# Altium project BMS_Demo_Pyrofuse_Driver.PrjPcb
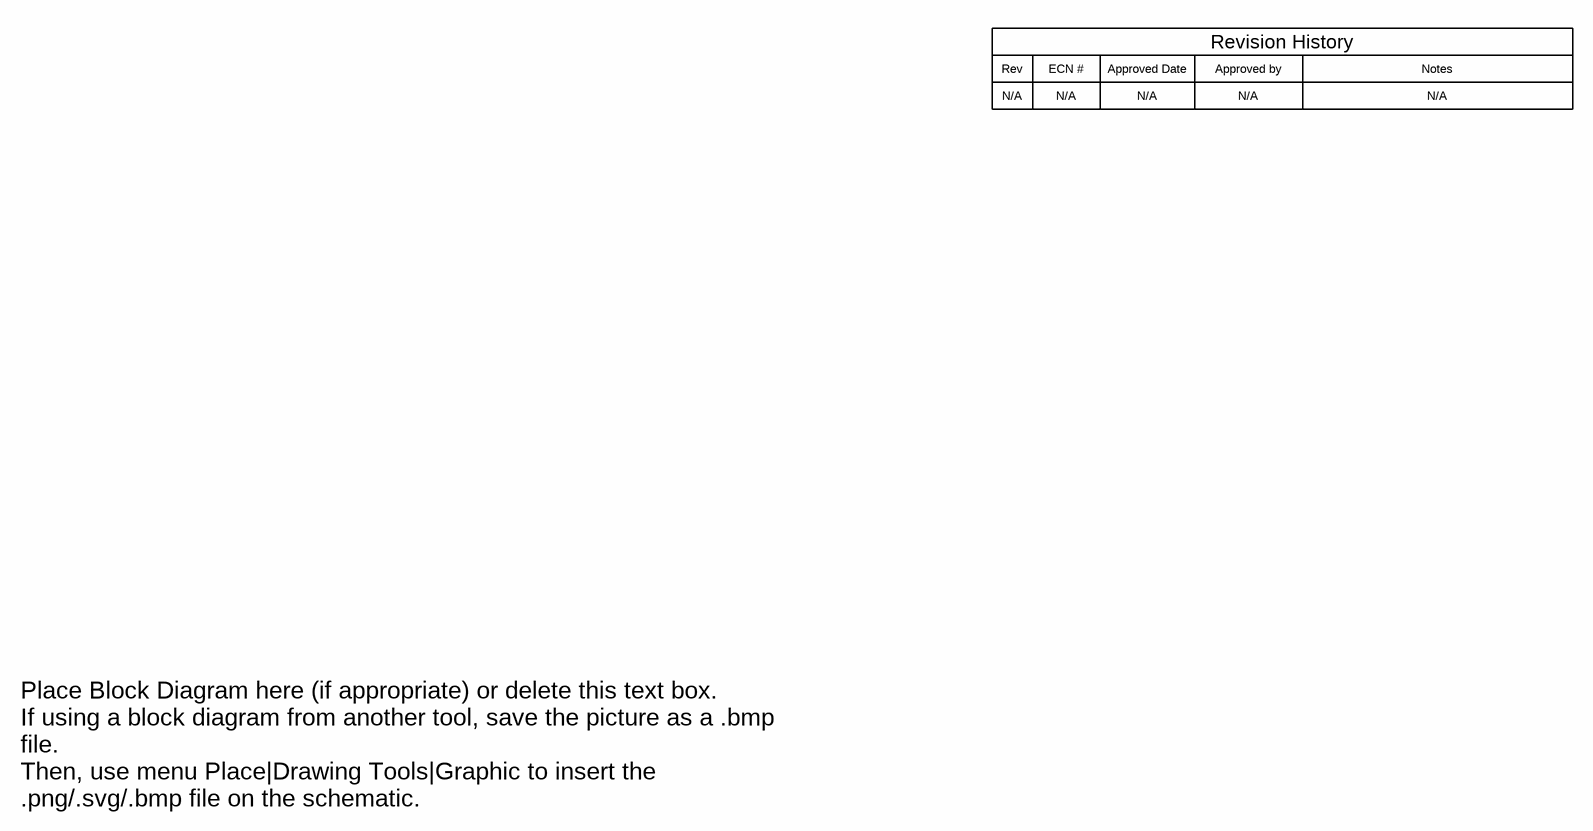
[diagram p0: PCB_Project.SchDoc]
CopyrightYear: 2022; PCB_Layout: A0497701; PCB_Rev: E1; PRJ_Customer: Public Release; PRJ_Engineer: Bing Zou; PRJ_Number: AUTOSYS-783; PRJ_Title: PYROFUSE DRIVER; SCH_Rev: E1; TechSupport: http://www.ti.com/support; TID: N/A
3 sheets, 67 parts. Net scope: global (net labels, ports and power ports of the same name join across sheets).
Board file: BMS_Demo_Pyrofuse_Driver_PCB.PcbDoc
Sheets:
  PCB_Project.SchDoc
  BMS_Demo_Pyrofuse_Driver_Schematic.SchDoc
  BMS_Demo_Pyrufose_Driver_Hardware.SchDoc

## Sheet PCB_Project.SchDoc
size 431 x 279 mm; Date: Not shown in title block; ApprovedBy: Not shown in title block; CheckedBy: Not shown in title block; Author: Not shown in title block; CompanyName: Not shown in title block; Engineer: Not shown in title block; Organization: Not shown in title block; Address1: Not shown in title block; Address2: Not shown in title block; Address3: Not shown in title block; Address4: Not shown in title block; DocumentNumber: 1; Revision: Use project parameter SCH_Rev; SheetNumber: 1; SheetTotal: 3; PageSetup: Record=PageOptions¦CenterHorizontal=True¦CenterVertical=True¦PrintScale=1.00¦XCorrection=1.00¦YCorrection=1.00¦PrintKind=0¦BorderSize=5000000¦LeftOffset=0¦BottomOffset=0¦Orientation=2¦PaperLength=1000¦PaperWidth=1000¦Scale=100¦PaperSource=15¦PrintQuality=600¦MediaType=1¦DitherType=10¦PaperKind=Letter¦PrintScaleMode=1

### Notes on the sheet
- Rev
- N/A
- ECN #
- Approved Date
- Approved by
- Revision History
- Notes
- Place Block Diagram here (if appropriate) or delete this text box.
  If using a block diagram from another tool, save the picture as a .bmp file.
  Then, use menu Place|Drawing Tools|Graphic to insert the .png/.svg/.bmp file on the schematic.

## Sheet BMS_Demo_Pyrofuse_Driver_Schematic.SchDoc
size 431 x 279 mm; Date: Not shown in title block; ApprovedBy: Not shown in title block; CheckedBy: Not shown in title block; Author: Not shown in title block; CompanyName: Not shown in title block; Engineer: Not shown in title block; Organization: Not shown in title block; Address1: Not shown in title block; Address2: Not shown in title block; Address3: Not shown in title block; Address4: Not shown in title block; DocumentNumber: 2; Revision: Use project parameter SCH_Rev; SheetNumber: 2; SheetTotal: 3; PageSetup: Record=PageOptions¦CenterHorizontal=True¦CenterVertical=True¦PrintScale=1.00¦XCorrection=1.00¦YCorrection=1.00¦PrintKind=0¦BorderSize=5000000¦LeftOffset=0¦BottomOffset=0¦Orientation=2¦PaperLength=1000¦PaperWidth=1000¦Scale=100¦PaperSource=15¦PrintQuality=600¦MediaType=1¦DitherType=10¦PaperKind=Letter¦PrintScaleMode=1
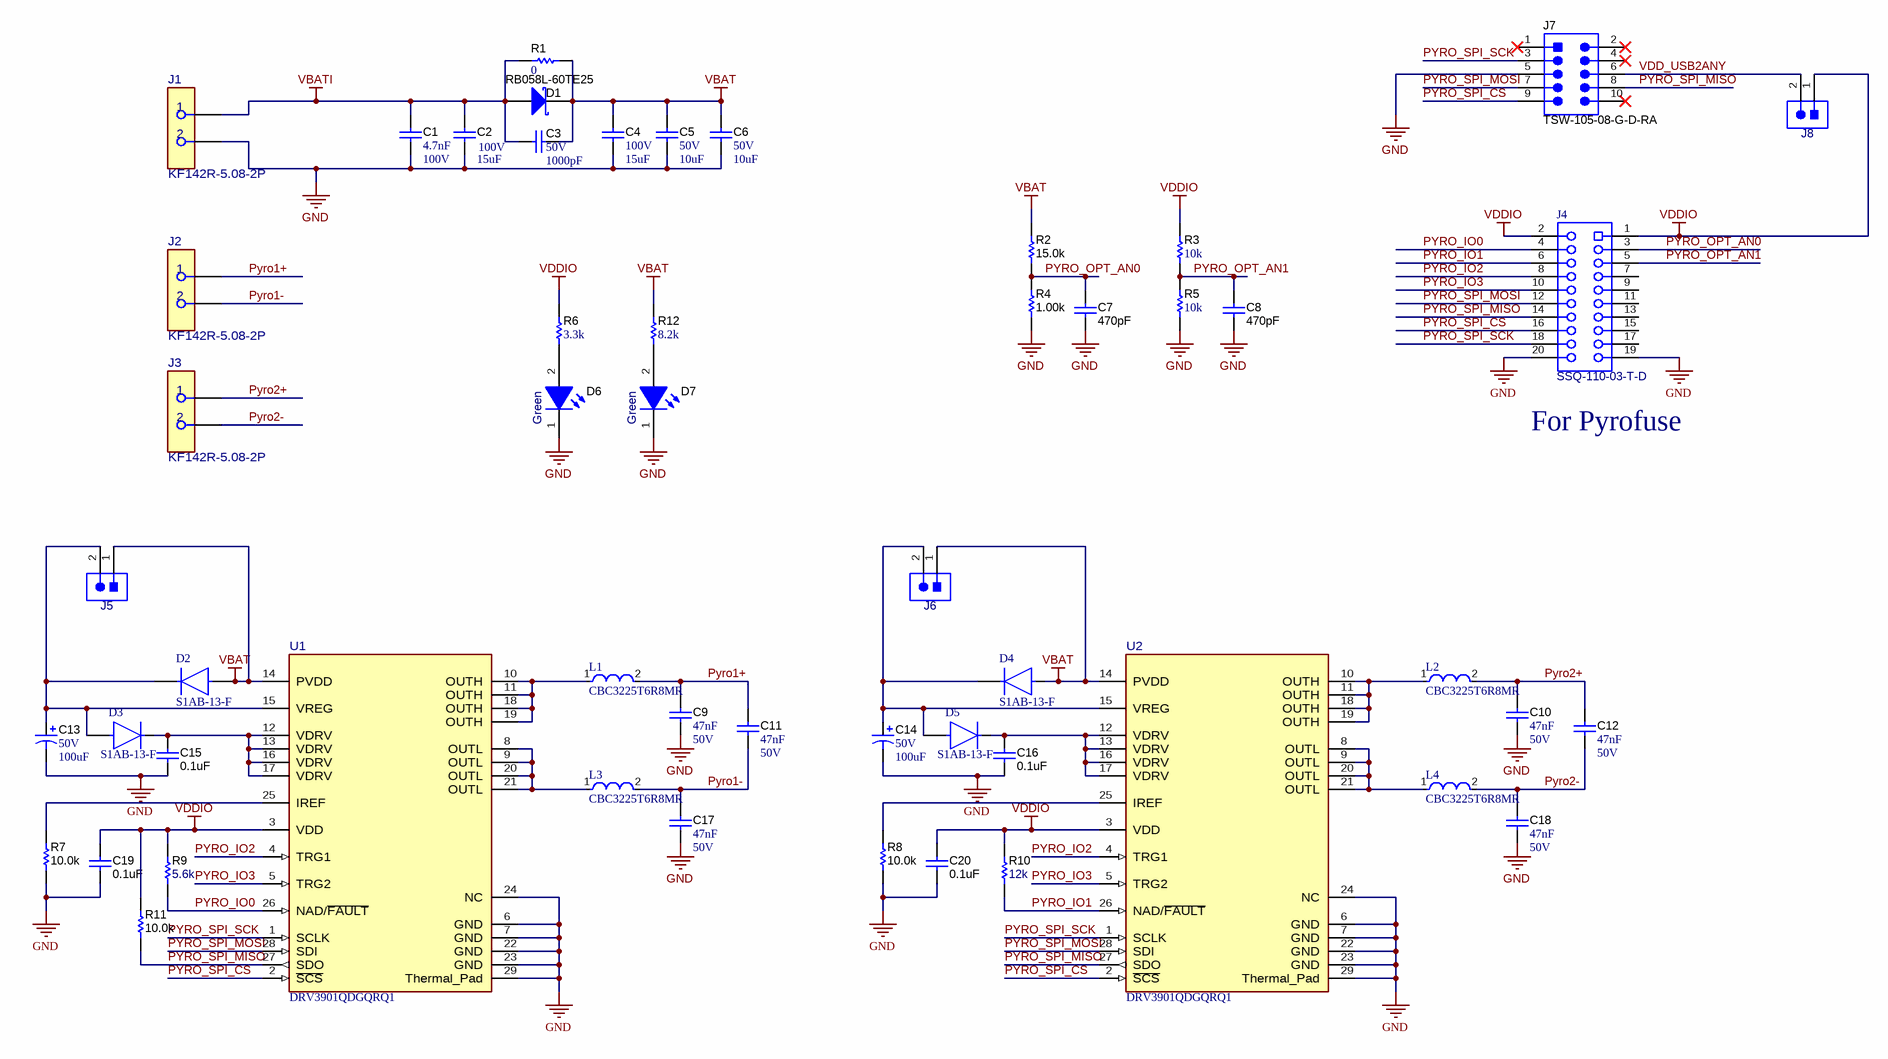
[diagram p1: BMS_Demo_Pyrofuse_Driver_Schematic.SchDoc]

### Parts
C1  Cap_F: 4.7nF  VDC_V: 100V  [0603]  (hidden comment: CGA3E2X7R2A472K080AA)
C2  VDC_V: 100V  ValueDisplayed: 15uF  [2220_280]  (hidden comment: CGA9P3X7S2A156M250KB)
C3  VDC_V: 50V  ValueDisplayed: 1000pF  [0402]  (hidden comment: GRM1555C1H102JA01D)
C4  VDC_V: 100V  ValueDisplayed: 15uF  [2220_280]  (hidden comment: CGA9P3X7S2A156M250KB)
C5  VDC_V: 50V  ValueDisplayed: 10uF  [1210_280]  (hidden comment: CGA6P3X7S1H106K250AB)
C6  VDC_V: 50V  ValueDisplayed: 10uF  [1210_280]  (hidden comment: CGA6P3X7S1H106K250AB)
C7  ValueDisplayed: 470pF  [0402L]  (hidden comment: GRM155R71H471KA01D)
C8  ValueDisplayed: 470pF  [0402L]  (hidden comment: GRM155R71H471KA01D)
C9  Cap_F: 47nF  VDC_V: 50V  [0603]  (hidden comment: CGA3E2X7R1H473K080AA)
C10  Cap_F: 47nF  VDC_V: 50V  [0603]  (hidden comment: CGA3E2X7R1H473K080AA)
C11  Cap_F: 47nF  VDC_V: 50V  [0603]  (hidden comment: CGA3E2X7R1H473K080AA)
C12  Cap_F: 47nF  VDC_V: 50V  [0603]  (hidden comment: CGA3E2X7R1H473K080AA)
C13  VDC_V: 50V  ValueDisplayed: 100uF  [Chemi-Con_800x1200]  (hidden comment: ELXZ500ELL101MH12D)
C14  VDC_V: 50V  ValueDisplayed: 100uF  [Chemi-Con_800x1200]  (hidden comment: ELXZ500ELL101MH12D)
C15  ValueDisplayed: 0.1uF  [0402L]  (hidden comment: C1005X7R1H104K050BE)
C16  ValueDisplayed: 0.1uF  [0402L]  (hidden comment: C1005X7R1H104K050BE)
C17  Cap_F: 47nF  VDC_V: 50V  [0603]  (hidden comment: CGA3E2X7R1H473K080AA)
C18  Cap_F: 47nF  VDC_V: 50V  [0603]  (hidden comment: CGA3E2X7R1H473K080AA)
C19  ValueDisplayed: 0.1uF  [0402L]  (hidden comment: C1005X7R1H104K050BE)
C20  ValueDisplayed: 0.1uF  [0402L]  (hidden comment: C1005X7R1H104K050BE)
D1  RB058L-60TE25  [SMA]
D2  S1AB-13-F  [FP-SMB-MFG]
D3  S1AB-13-F  [FP-SMB-MFG]
D4  S1AB-13-F  [FP-SMB-MFG]
D5  S1AB-13-F  [FP-SMB-MFG]
D6  value Green  [WL-SMCW_GREEN]  (hidden comment: 150060VS75000)
D7  value Green  [WL-SMCW_GREEN]  (hidden comment: 150060VS75000)
J1  KF142R-5.08-2P  [FP-KF142R-5.08-2P_HDR2-MFG]
J2  KF142R-5.08-2P  [FP-KF142R-5.08-2P_HDR2-MFG]
J3  KF142R-5.08-2P  [FP-KF142R-5.08-2P_HDR2-MFG]
J4  SSQ-110-03-T-D  [Samtec_SSQ-110-03-x-D]
J5  PEC02SAAN  [CONN_PEC02SAAN]  (value not drawn)
J6  PEC02SAAN  [CONN_PEC02SAAN]  (value not drawn)
J7  TSW-105-08-G-D-RA  [Samtec_TSW-105-08-G-D-RA]
J8  PEC02SAAN  [CONN_PEC02SAAN]  (value not drawn)
L1  CBC3225T6R8MR  [FP-CB3225-MFG]
L2  CBC3225T6R8MR  [FP-CB3225-MFG]
L3  CBC3225T6R8MR  [FP-CB3225-MFG]
L4  CBC3225T6R8MR  [FP-CB3225-MFG]
R1  ValueDisplayed: 0  [2512]  (hidden comment: CRCW25120000Z0EG)
R2  ValueDisplayed: 15.0k  [0402L]  (hidden comment: RC0402FR-0715KL)
R3  ValueDisplayed: 10k  [0402]  (hidden comment: CRCW040210K0JNED)
R4  ValueDisplayed: 1.00k  [0402L]  (hidden comment: RC0402FR-071KL)
R5  ValueDisplayed: 10k  [0402]  (hidden comment: CRCW040210K0JNED)
R6  ValueDisplayed: 3.3k  [0603]  (hidden comment: CRCW06033K30JNEA)
R7  ValueDisplayed: 10.0k  [0402]  (hidden comment: CRCW040210K0FKED)
R8  ValueDisplayed: 10.0k  [0402]  (hidden comment: CRCW040210K0FKED)
R9  ValueDisplayed: 5.6k  [0402L]  (hidden comment: CRCW04025K60JNED)
R10  ValueDisplayed: 12k  [0402L]  (hidden comment: CRCW040212K0JNED)
R11  ValueDisplayed: 10.0k  [0402]  (hidden comment: CRCW040210K0FKED)
R12  ValueDisplayed: 8.2k  [0603]  (hidden comment: CRCW06038K20JNEA)
U1  DRV3901QDGQRQ1  [DGQ0028A-MFG]
U2  DRV3901QDGQRQ1  [DGQ0028A-MFG]

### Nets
GND: C1.2 C2.2 C4.2 C5.2 C6.2 C7.2 C8.2 C9.2 C10.2 C13.2(-) C14.2(-) C15.2 C16.2 C17.2 C18.2 C19.1 C20.1 D6.1(K) D7.1(K) J1.2 J4.19 J4.20 J7.5 R4.1 R5.1 R7.1 R8.1 U1.6(GND) U1.7(GND) U1.22(GND) U1.23(GND) U1.24(NC) U1.29(Thermal_Pad) U2.6(GND) U2.7(GND) U2.22(GND) U2.23(GND) U2.24(NC) U2.29(Thermal_Pad)
VBAT: C3.1 C4.1 C5.1 C6.1 D1.1(K) D2.2(A) D4.2(A) J5.1 J6.1 R1.2 R2.2 R12.2 U1.14(PVDD) U2.14(PVDD)
VBATI: C1.1 C2.1 C3.2 D1.2(A) J1.1 R1.1
VDDIO: C19.2 C20.2 J4.1 J4.2 J8.1 R3.2 R6.2 R9.2 R10.2 R11.2 U1.3(VDD) U2.3(VDD)
Pyro1+: C9.1 C11.1 J2.1 L1.2
Pyro1-: C11.2 C17.1 J2.2 L3.2
Pyro2+: C10.1 C12.1 J3.1 L2.2
Pyro2-: C12.2 C18.1 J3.2 L4.2
PYRO_IO0: J4.4 R9.1 U1.26(NAD/~{FAULT})
PYRO_IO1: J4.6 R10.1 U2.26(NAD/~{FAULT})
PYRO_IO2: J4.8 U1.4(TRG1) U2.4(TRG1)
PYRO_IO3: J4.10 U1.5(TRG2) U2.5(TRG2)
PYRO_OPT_AN0: C7.1 J4.3 R2.1 R4.2
PYRO_OPT_AN1: C8.1 J4.5 R3.1 R5.2
PYRO_SPI_CS: J4.16 J7.9 U1.2(~{SCS}) U2.2(~{SCS})
PYRO_SPI_MISO: J4.14 J7.8 R11.1 U1.27(SDO) U2.27(SDO)
PYRO_SPI_MOSI: J4.12 J7.7 U1.28(SDI) U2.28(SDI)
PYRO_SPI_SCK: J4.18 J7.3 U1.1(SCLK) U2.1(SCLK)
VDD_USB2ANY: J7.6 J8.2
NetC13_1: C13.1(+) D2.1(C) D3.2(A) J5.2 U1.15(VREG)
NetC14_1: C14.1(+) D4.1(C) D5.2(A) J6.2 U2.15(VREG)
NetC15_1: C15.1 D3.1(C) U1.12(VDRV) U1.13(VDRV) U1.16(VDRV) U1.17(VDRV)
NetC16_1: C16.1 D5.1(C) U2.12(VDRV) U2.13(VDRV) U2.16(VDRV) U2.17(VDRV)
NetD6_2: D6.2(A) R6.1
NetD7_2: D7.2(A) R12.1
NetL1_1: L1.1 U1.10(OUTH) U1.11(OUTH) U1.18(OUTH) U1.19(OUTH)
NetL2_1: L2.1 U2.10(OUTH) U2.11(OUTH) U2.18(OUTH) U2.19(OUTH)
NetL3_1: L3.1 U1.8(OUTL) U1.9(OUTL) U1.20(OUTL) U1.21(OUTL)
NetL4_1: L4.1 U2.8(OUTL) U2.9(OUTL) U2.20(OUTL) U2.21(OUTL)
NetR7_2: R7.2 U1.25(IREF)
NetR8_2: R8.2 U2.25(IREF)

Not connected (* = marked no-connect by the designer): J4 7 9 11 13 15 17; J7 1* 2* 4* 10*

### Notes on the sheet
- (near J4) For Pyrofuse

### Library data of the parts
C1 = CMP-0007088-4: CAP, CERM, 4700 pF, 100 V, +/- 10%, X7R, AEC-Q200 Grade 1, 0603; Manufacturer: TDK; TaMin_C: -55°C; ESR_ohm: 0.469862; Polarized: N; SizeAreaWB_mm2: 4.68; Value1: 0.469862 ohm; U/M: EA; Value: 4700pF; TaMax_C: 125°C; SizeZ_mm: 1; SizeX_mm: 1.6; SizeY_mm: 0.8; SizeArea_mm2: 1.28; AEC Qualified: Y; IRMS_A: 323.35mA; AEC Category: Q200
C2 C4 = CMP-0009420-2: CAP, CERM, 15 uF, 100 V, +/- 20%, X7S, AEC-Q200 Grade 1, 2220; Manufacturer: TDK; TaMin_C: -55°C; ESR_ohm: 2.642m; Polarized: N; SizeAreaWB_mm2: 53.9; Value1: 0.002642 ohm; U/M: EA; Value: 15uF; TaMax_C: 125°C; SizeZ_mm: 2.8; SizeX_mm: 5.7; SizeY_mm: 5; SizeArea_mm2: 28.5; AEC Qualified: Y; Cap_F: 15µF; IRMS_A: 5.61617A; AEC Grade: 1; AEC Category: Q200
C3 = CMP-0006412-2: CAP, CERM, 1000 pF, 50 V, +/- 5%, C0G/NP0, 0402; Manufacturer: MuRata; TaMin_C: -55°C; Polarized: N; SizeAreaWB_mm2: 3; Value1: Unknown; U/M: EA; Value: 1000pF; TaMax_C: 125°C; SizeZ_mm: 0.6; SizeX_mm: 1; SizeY_mm: 0.5; Cap_F: 1nF; AEC Category: Q200
C5 C6 = CMP-0009164-2: CAP, CERM, 10 uF, 50 V, +/- 10%, X7S, AEC-Q200 Grade 1, 1210; Manufacturer: TDK; TaMin_C: -55°C; ESR_ohm: 2.827m; Polarized: N; SizeAreaWB_mm2: 14.7; Value1: 0.002827 ohm; U/M: EA; Value: 10uF; TaMax_C: 125°C; SizeZ_mm: 2.8; SizeX_mm: 3.2; SizeY_mm: 2.5; SizeArea_mm2: 8; AEC Qualified: Y; Cap_F: 10µF; IRMS_A: 4.37286A; AEC Grade: 1; AEC Category: Q200
C7 C8 = CMP-0006691-2: CAP, CERM, 470 pF, 50 V, +/- 10%, X7R, 0402; Manufacturer: MuRata; TaMin_C: -55°C; Polarized: N; SizeAreaWB_mm2: 3; Value1: Unknown; U/M: EA; Value: 470pF; TaMax_C: 125°C; SizeZ_mm: 0.6; SizeX_mm: 1; SizeY_mm: 0.5; Cap_Case: 0402; Value2: 50V; AEC Category: Q200
C9-C12 C17 C18 = CMP-0007079-4: CAP, CERM, 0.047 uF, 50 V, +/- 10%, X7R, AEC-Q200 Grade 1, 0603; Manufacturer: TDK; TaMin_C: -55°C; ESR_ohm: 0.049007; Polarized: N; SizeAreaWB_mm2: 4.68; Value1: 0.049007 ohm; U/M: EA; TaMax_C: 125°C; SizeZ_mm: 1; SizeX_mm: 1.6; SizeY_mm: 0.8; SizeArea_mm2: 1.28; AEC Qualified: Y; IRMS_A: 7.67528dA; AEC Category: Q200
C13 C14 = CMP-0009893-2: CAP, AL, 100 uF, 50 V, +/- 20%, AEC-Q200 Grade 2, TH; Manufacturer: Chemi-Con; TaMin_C: -55°C; Polarized: Y; SizeAreaWB_mm2: 100; Value1: Unknown; U/M: EA; Value: 100uF; TaMax_C: 105°C; SizeZ_mm: 13.5; SizeX_mm: 8; Cap_Case: 8x12mm; SizeArea_mm2: 64; CompType: Capacitor; Cap_F: 100µF; IRMS_A: 4.85dA; AEC Grade: 2; AEC Category: Q200
C15 C16 C19 C20 = CMP-0064946-2: CAP, CERM, 0.1 uF, 50 V,+/- 10%, X7R, 0402; Manufacturer: TDK; TaMin_C: -55°C; Polarized: N; SizeAreaWB_mm2: 3; Value1: Unknown; U/M: EA; Value: 0.1uF; TaMax_C: 125°C; SizeZ_mm: 0.6; SizeX_mm: 1; SizeY_mm: 0.5; Cap_Case: 0402; Value2: 50V; Cap_F: 100nF; AEC Category: Q200
D1 = CMP-0028854-2: Diode, Schottky, 60 V, 3 A, AEC-Q101, SMA; Manufacturer: Rohm; Value1: 3A; AEC Category: Q101; Green_REACh: Incomplete; TJmax_C: 150°C; SizeArea_mm2: 16.3228; Vf_V: 640mV; SizeZ_mm: 2.87; Value2: 0.64V; Value: 60V; SizeX_mm: 5.59; AEC Qualified: Y; Green_Lifecycle: Not Set; SizeAreaWB_mm2: 37.3428; SizeY_mm: 2.92
D2-D5 = CMP-0586-00001-3: DIODE GEN PURP 50V 1A SMB; Element Configuration: Single; Max Surge Current: 30A; Polarity: Standard; Recovery Time: 1.8us; Forward Voltage: 1.1V; Capacitance: 10pF; Peak Reverse Current: 5uA
D6 D7 = CMP-0002894-2: LED, Green, SMD; Manufacturer: Wurth Elektronik; Type: AlInGaP; Value2: 2V; Io_A: 20mA; Value1: W
J1-J3 = CMP-0122691-1: 1.5 5.08mm 14~22 15A 2P 250V 2 Push-Pull,P=5.08mm Spring Clamp System Terminal Block ROHS; Manufacturer: Cixi Kefa Electronics; ContactFinish: Tin; Current_A: 10A; Row_Count: 1; Voltage_V: 300V; AEC Qualified: No; Conn Gender: Female; Conn Orientation: Horizontal; Is Female: yes; Max Wire Gauge: 14; Min Wire Gauge: 22; SizeZ_mm: 14.2mm
J4 = CMP-0079854-1: Receptacle, 2.54mm, 10x2, Tin, TH; Manufacturer: Samtec; Cert_VDE: N; Current_A: 6.3A; Green_Lifecycle: Active; Gender: Female; Cert_CSA: Y; Green_REACh: Incomplete; Voltage_V: 550V; CompType: Socket Strip; Row_Count: 2; RowSpacing_mm: 2.54
J5 J6 J8 = CMP-0002337-1: Header, 100mil, 2x1, Tin, TH; Manufacturer: Sullins Connector Solutions; CNHeader: TRUE; Current_A: 3A; Green_Lifecycle: Not Set; Shrouded: N; Gender: Male; Green_REACh: Incomplete; Voltage_V: 1.8kV; Row_Count: 1; Pitch_mm: 2.54; CT: FALSE; Cert_UL: Y
J7 = CMP-0075472-2: Header, 100mil, 5x2, Gold, R/A, TH; Manufacturer: Samtec; Pitch_mm: 2.54; Cert_VDE: N; Gender: Male; Cert_CSA: Y; Voltage_V: 550V; Green_REACh: Passed; Current_A: 6.3A; Green_Lifecycle: Active; Row_Count: 2
L1-L4 = CMP-14484-000108-1: SMD Inductors 6.8uH ±20% 0.94A 0.156Ω 1210; Core Material: Ferrite; Current Rating: 940mA; DC Resistance (DCR): 156mR; Shielding: Unshielded; Test Frequency: 100kHz; Max DC Current: 950mA; Saturation Current: 930mA; Self Resonant Frequency: 50MHz
R1 = CMP-0015864-3: RES, 0, 5%, 1 W, AEC-Q200 Grade 0, 2512; Manufacturer: Vishay-Dale; Power_W: 1W; TempCo: ppm/C; Value_Code: 0000; Value: 0; EIA_Code: E24; SizeX_mm: 6.3; SizeY_mm: 3.2; SizeZ_mm: 0.71; SizeArea_mm2: 20.16; AEC Qualified: Y; AEC Category: Q200
R2 = CMP-0078583-1: RES, 15.0 k, 1%, 0.063 W, 0402; Manufacturer: Yageo America; Power_W: 63mW; Green_Lifecycle: Active; TempCo: 100 ppm/C; Value_Code: 15k0; Green_REACh: Passed; Value: 15.0k; EIA_Code: E96; Res_ohm: 15k; SizeX_mm: 1; SizeY_mm: 0.5; SizeZ_mm: 0.6; Value2: 0.063W; AEC Qualified: N; AEC Category: Q200
R3 R5 = CMP-0026825-5: RES, 10 k, 5%, 0.063 W, AEC-Q200 Grade 0, 0402; Manufacturer: Vishay-Dale; Power_W: 63mW; TempCo: 200 ppm/C; Value_Code: 10k0; Value: 10k; EIA_Code: E24; SizeX_mm: 1; SizeY_mm: 0.5; SizeZ_mm: 0.6; Value2: 0.063W; AEC Qualified: Y; VDC_V: 50V; AEC Category: Q200; AEC Grade: 0
R4 = CMP-0026725-1: RES, 1.00 k, 1%, 0.0625 W, 0402; Manufacturer: Yageo America; Power_W: 62.5mW; TempCo: 100 ppm/C; Value_Code: 1k00; U/M: EA; Value: 1.00k; EIA_Code: E96; Res_ohm: 1k; SizeX_mm: 1; SizeY_mm: 0.5; SizeZ_mm: 0.6; AEC Qualified: N; VDC_V: 50V; AEC Category: Q200
R6 = CMP-0025797-4: RES, 3.3 k, 5%, 0.1 W, AEC-Q200 Grade 0, 0603; Manufacturer: Vishay-Dale; Power_W: 100mW; TempCo: 200 ppm/C; Value_Code: 3k30; Value: 3.3k; EIA_Code: E24; SizeX_mm: 1.6; SizeY_mm: 0.8; SizeZ_mm: 1; Value2: 0.1W; SizeArea_mm2: 1.28; AEC Qualified: Y; VDC_V: 75V; AEC Category: Q200; AEC Grade: 0
R7 R8 R11 = CMP-0025958-3: RES, 10.0 k, 1%, 0.063 W, AEC-Q200 Grade 0, 0402; Manufacturer: Vishay-Dale; Power_W: 63mW; TempCo: 100 ppm/C; Value_Code: 10k0; Value: 10.0k; EIA_Code: E96; Res_ohm: 10k; SizeX_mm: 1; SizeY_mm: 0.5; SizeZ_mm: 0.6; Value2: 0.063W; AEC Qualified: Y; VDC_V: 50V; AEC Category: Q200; AEC Grade: 0
R9 = CMP-0026952-5: RES, 5.6 k, 5%, 0.063 W, AEC-Q200 Grade 0, 0402; Manufacturer: Vishay-Dale; Power_W: 63mW; TempCo: 200 ppm/C; Value_Code: 5k60; Value: 5.6k; EIA_Code: E24; SizeX_mm: 1; SizeY_mm: 0.5; SizeZ_mm: 0.6; Value2: 0.063W; AEC Qualified: Y; VDC_V: 50V; AEC Category: Q200; AEC Grade: 0
R10 = CMP-0026834-3: RES, 12 k, 5%, 0.063 W, AEC-Q200 Grade 0, 0402; Manufacturer: Vishay-Dale; Power_W: 63mW; TempCo: 200 ppm/C; Value_Code: 12k0; Value: 12k; EIA_Code: E24; SizeX_mm: 1; SizeY_mm: 0.5; SizeZ_mm: 0.6; Value2: 0.063W; AEC Qualified: Y; VDC_V: 50V; AEC Category: Q200; AEC Grade: 0
R12 = CMP-0025862-4: RES, 8.2 k, 5%, 0.1 W, AEC-Q200 Grade 0, 0603; Manufacturer: Vishay-Dale; Power_W: 100mW; TempCo: 200 ppm/C; Value_Code: 8k20; Value: 8.2k; EIA_Code: E24; SizeX_mm: 1.6; SizeY_mm: 0.8; SizeZ_mm: 1; Value2: 0.1W; SizeArea_mm2: 1.28; AEC Qualified: Y; VDC_V: 75V; AEC Category: Q200; AEC Grade: 0
U1 U2 = CMP-0095728-2: 1 Channel, 12-V Automotive Pyro-fuse Driver with Functional Safety; Manufacturer: Texas Instruments; SizeZ_mm: 1.1mm; AEC Grade: Grade 1; AEC Qualified: Yes; CompType: IC; Standoff Height: 0mm; AEC Category: Q200

## Sheet BMS_Demo_Pyrufose_Driver_Hardware.SchDoc
size 431 x 279 mm; Date: Not shown in title block; ApprovedBy: Not shown in title block; CheckedBy: Not shown in title block; Author: Not shown in title block; CompanyName: Not shown in title block; Engineer: Not shown in title block; Organization: Not shown in title block; Address1: Not shown in title block; Address2: Not shown in title block; Address3: Not shown in title block; Address4: Not shown in title block; DocumentNumber: 3; Revision: Use project parameter SCH_Rev; SheetNumber: 3; SheetTotal: 3; PageSetup: Record=PageOptions¦CenterHorizontal=True¦CenterVertical=True¦PrintScale=1.00¦XCorrection=1.00¦YCorrection=1.00¦PrintKind=0¦BorderSize=5000000¦LeftOffset=0¦BottomOffset=0¦Orientation=2¦PaperLength=1000¦PaperWidth=1000¦Scale=100¦PaperSource=15¦PrintQuality=600¦MediaType=1¦DitherType=10¦PaperKind=Letter¦PrintScaleMode=1
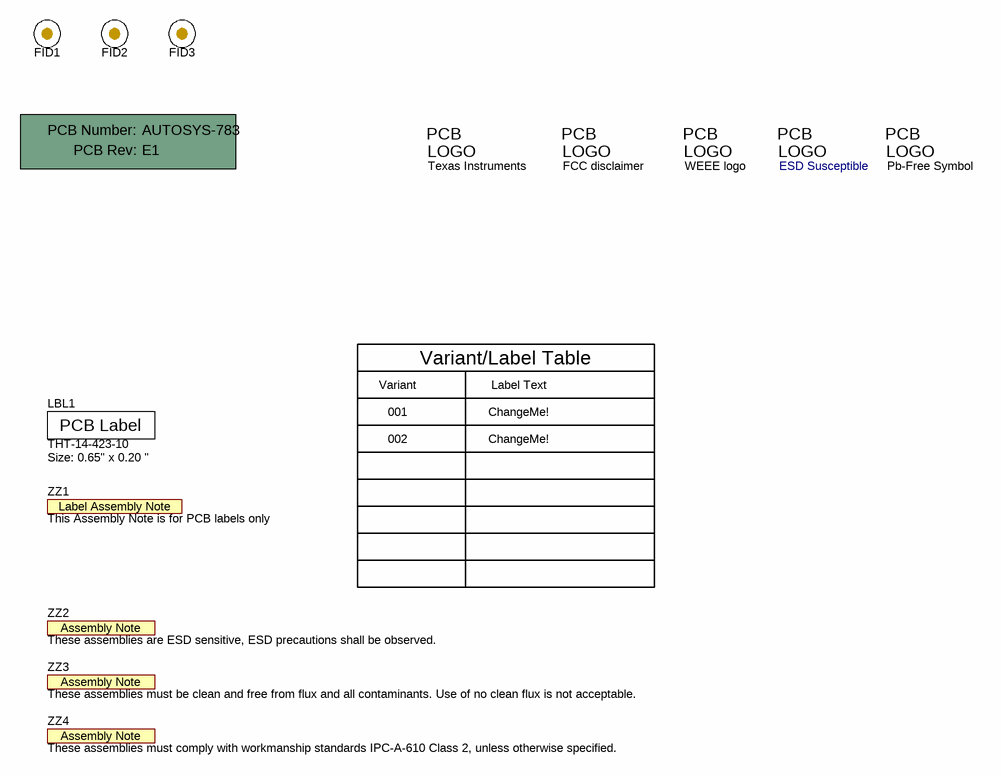
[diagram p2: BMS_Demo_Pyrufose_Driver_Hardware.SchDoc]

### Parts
!PCB  Printed Circuit Board  (value not drawn)  (mechanical)
FID1  Fiducial  [Fiducial10-20]  (value not drawn)
FID2  Fiducial  [Fiducial10-20]  (value not drawn)
FID3  Fiducial  [Fiducial10-20]  (value not drawn)
LBL1  THT-14-423-10  Note: Size: 0.65" x 0.20 "  [Label_650x200]
Logo1  Texas Instruments  [TI_Stacked_Overlay_Small]  (no BOM)
Logo2  ESD Susceptible  [ESD_Overlay_Medium]  (no BOM)
Logo3  FCC disclaimer  [FCC_disclaimer]  (no BOM)
Logo4  WEEE logo  [WEEE_Minimum]  (no BOM)
Logo5  Pb-Free Symbol  [Pb-Free_Overlay_Medium]  (no BOM)
ZZ1  This Assembly Note is for PCB labels only  [AssemblyNoteLabel]  (no BOM)
ZZ2  These assemblies are ESD sensitive, ESD precautions shall be observed.  [AssemblyNote]  (no BOM)
ZZ3  These assemblies must be clean and free from flux and all contaminants. Use of no clean flux is not acceptable.  [AssemblyNote]  (no BOM)
ZZ4  These assemblies must comply with workmanship standards IPC-A-610 Class 2, unless otherwise specified.  [AssemblyNote]  (no BOM)

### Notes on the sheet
- Variant
- Variant/Label Table
- Label Text
- 001
- 002
- ChangeMe!

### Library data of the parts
!PCB = CMP-0003618-2: Manufacturer: Any; PartNumber: AUTOSYS-783
FID1-FID3 = CMP-0077181-1: Fiducial mark.  There is nothing to buy or mount.
LBL1 = CMP-0003625-1: Thermal Transfer Printable Labels, 0.650" W x 0.200" H - 10,000 per roll; Manufacturer: Brady; CompType: Label
Logo1 = CMP-0074838-1: Texas Instrument Corporate Signature; SymbolCreator: a0412235; Lib Reference: TI_Logo; Library Reference: Logo
Logo2 = CMP-0074840-1: ESD Susceptible Symbol; SymbolCreator: a0412235; Lib Reference: ESD_Susceptible
Logo3 = CMP-0074847-1: FCC_disclaimer; Library Reference: Logo
Logo4 = CMP-0074769-1
Logo5 = CMP-0074839-1: SymbolCreator: a0412235
ZZ1 = CMP-0003616-3
ZZ2 = CMP-0077236-1
ZZ3 = CMP-0077237-1
ZZ4 = CMP-0077238-1

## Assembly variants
001: not fitted FID1 FID2 FID3 R1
